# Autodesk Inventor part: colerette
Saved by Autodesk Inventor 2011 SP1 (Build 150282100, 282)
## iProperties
Created: 2010-12
Part Number: colerette
Document SubType Name: Modeling
Designer: eric
Density: 1 g/cm^3
Author: eric
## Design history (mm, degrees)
feature "Base1"
node "Solide1"
node "Corps solides"
node "Corps surfaciques"
